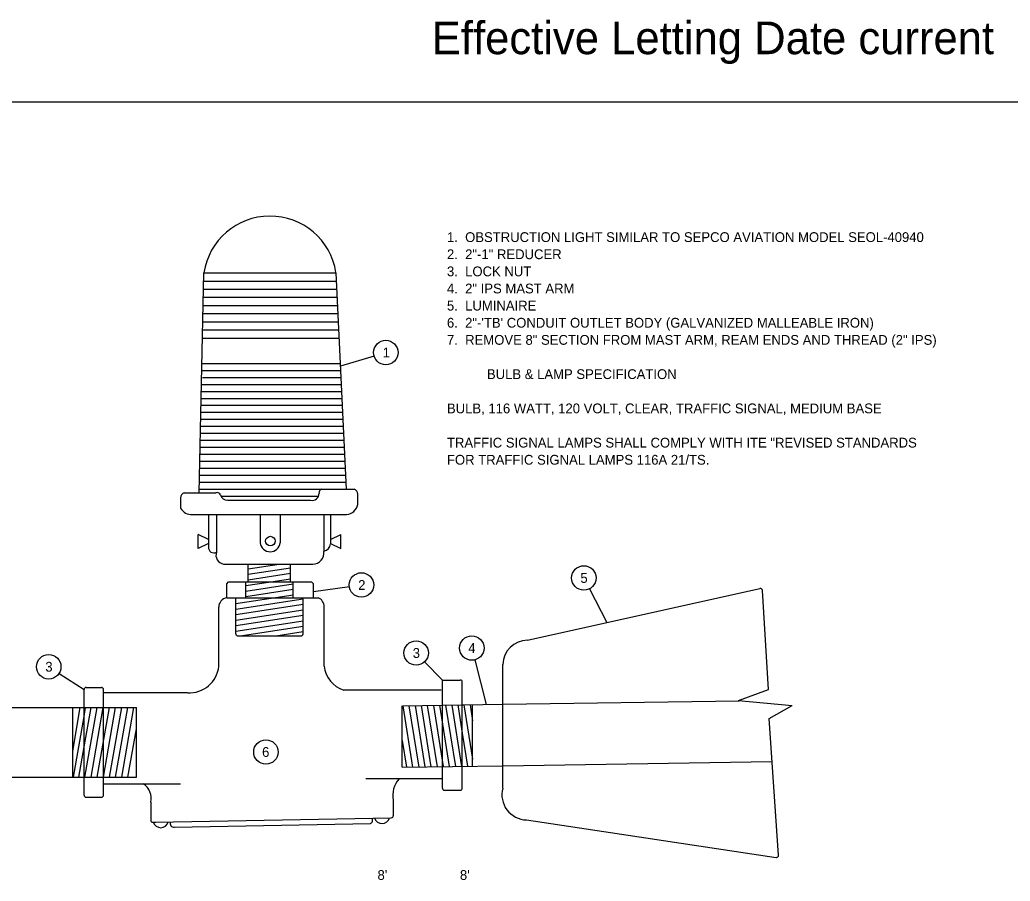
# Model space of a CAD drawing. Extents: x 99968 to 128667, y 90163 to 102182.
# Drawn here: x 106253 to 107468, y 101126 to 102182 of the extents above; entities that cross this region are included whole.
import ezdxf

# ---------------------------------------------------------------- set-up
doc = ezdxf.new("R2010")
doc.units = 0
for name, color, linetype in [('Default', 7, 'Continuous'), ('Level 7', 7, 'Continuous'), ('RD Standard Plans Active', 7, 'Continuous')]:
    doc.layers.add(name, color=color, linetype=linetype)

msp = doc.modelspace()

# ---------------------------------------------------------------- linework, layer by layer
at = {"layer": 'Default'}
msp.add_lwpolyline([(105067.5, 102081.5), (108267.2, 102081.5), (108267.2, 99881.9), (105067.5, 99881.9)], close=True, dxfattribs=at)
at = {"layer": 'RD Standard Plans Active'}
for p, q in [((106473.5, 101602.3), (106479.2, 101871.9)), ((106479.2, 101871.9), (106641.4, 101871.9)), ((106654.3, 101606.8), (106641.4, 101871.9)), ((106479.2, 101861.9), (106641.9, 101861.9)), ((106479.2, 101851.9), (106642.4, 101851.9)), ((106479.2, 101841.9), (106642.8, 101841.9)), ((106478.2, 101821.9), (106643.8, 101821.9)), ((106479.2, 101831.9), (106643.3, 101831.9)), ((106478, 101811.9), (106644.3, 101811.9)), ((106477.8, 101801.9), (106644.8, 101801.9)), ((106477.5, 101791.9), (106645.3, 101791.9)), ((106477.5, 101760.9), (106646.8, 101760.9)), ((106688, 101769.8), (106647, 101757.3)), ((106477.5, 101752.3), (106647.2, 101752.3)), ((106477.5, 101743.7), (106647.6, 101743.7)), ((106476.2, 101726.6), (106648.5, 101726.6)), ((106476.3, 101735.2), (106648.1, 101735.2)), ((106476, 101718), (106648.9, 101718)), ((106475.6, 101700.9), (106649.7, 101700.9)), ((106475.8, 101709.5), (106649.3, 101709.5)), ((106475.4, 101692.4), (106650.1, 101692.4)), ((106475.1, 101675.2), (106651, 101675.2)), ((106475.3, 101683.8), (106650.6, 101683.8)), ((106474.9, 101666.7), (106651.4, 101666.7)), ((106474.7, 101658.1), (106651.8, 101658.1)), ((106474.3, 101641), (106652.6, 101641)), ((106474.5, 101649.6), (106652.2, 101649.6)), ((106474.2, 101632.4), (106653.1, 101632.4)), ((106473.8, 101615.3), (106653.9, 101615.3)), ((106474, 101623.9), (106653.5, 101623.9)), ((106455, 101602.3), (106494.1, 101602.3)), ((106473.6, 101606.8), (106663.7, 101606.8)), ((106450.8, 101583.5), (106450.8, 101596.1)), ((106500.1, 101598.2), (106619.9, 101598.2)), ((106508.1, 101593.1), (106610.1, 101593.1)), ((106667.9, 101588), (106667.9, 101600.5)), ((106465, 101575.6), (106654.3, 101575.6)), ((106485, 101575.6), (106485, 101535.8)), ((106494.7, 101575.6), (106494.7, 101529.5)), ((106548.3, 101575.6), (106548.3, 101541)), ((106572.9, 101575.6), (106572.9, 101541)), ((106626.4, 101575.6), (106626.4, 101530.2)), ((106634.5, 101575.6), (106634.5, 101539.8)), ((106485, 101545.1), (106472.3, 101551.1)), ((106472.3, 101534), (106472.3, 101551.1)), ((106634.5, 101545.1), (106647.2, 101551.1)), ((106647.2, 101534), (106647.2, 101551.1)), ((106485, 101540.1), (106472.3, 101534)), ((106634.5, 101540.1), (106647.2, 101534)), ((106503.4, 101514.9), (106612.8, 101514.9)), ((106533.6, 101493.1), (106533.6, 101514.9)), ((106533.6, 101509), (106571.6, 101514.9)), ((106533.6, 101502.3), (106585.6, 101510.3)), ((106585.6, 101493.1), (106585.6, 101514.9)), ((106507.2, 101490.7), (106509.6, 101493.1)), ((106509.6, 101493.1), (106611.3, 101493.1)), ((106530.5, 101473.4), (106530.5, 101493.1)), ((106530.5, 101488.4), (106561.3, 101493.1)), ((106533.6, 101495.6), (106585.6, 101503.6)), ((106561.3, 101493.1), (106585.6, 101496.9)), ((106588.8, 101473.4), (106588.8, 101493.1)), ((106611.3, 101493.1), (106613.7, 101490.7)), ((106507.2, 101474.4), (106507.2, 101490.7)), ((106530.5, 101481.6), (106588.8, 101490.6)), ((106530.5, 101474.9), (106588.8, 101483.9)), ((106613.7, 101473.4), (106613.7, 101490.7)), ((106657.7, 101487), (106613.7, 101480.6)), ((106876.1, 101421.6), (107161.4, 101484.7)), ((106952.1, 101484.5), (106973.5, 101443.1)), ((107171.9, 101361.1), (107164.3, 101482.5)), ((106507.2, 101473.4), (106619.4, 101473.4)), ((106518.4, 101466.3), (106588.8, 101477.2)), ((106518.4, 101429.2), (106518.4, 101473.4)), ((106518.4, 101459.6), (106600.9, 101472.3)), ((106600.9, 101429.2), (106600.9, 101473.4)), ((106497.5, 101389.5), (106497.5, 101461.9)), ((106518.4, 101452.8), (106600.9, 101465.6)), ((106518.4, 101446.1), (106600.9, 101458.9)), ((106626.8, 101389.5), (106626.8, 101462.5)), ((106518.4, 101439.4), (106600.9, 101452.2)), ((106518.4, 101432.7), (106600.9, 101445.4)), ((106523.8, 101426.8), (106600.9, 101438.7)), ((106567.3, 101426.8), (106600.9, 101432)), ((106520.8, 101426.8), (106598.5, 101426.8)), ((106811.6, 101397.4), (106825.5, 101342.6)), ((106750, 101395), (106771.8, 101372.6)), ((106845.8, 101240), (106845.8, 101391.8)), ((106301.5, 101380.8), (106332.3, 101361.1)), ((106771.8, 101240), (106771.8, 101372.6)), ((106771.8, 101372.6), (106793.8, 101372.6)), ((106332.3, 101231.4), (106332.3, 101361.1)), ((106334.7, 101363.5), (106353.7, 101363.5)), ((106356.1, 101231.4), (106356.1, 101361.1)), ((106770.4, 101360.4), (106650.7, 101360.4)), ((106796.2, 101240), (106796.2, 101370.2)), ((107135.2, 101347.4), (107171.9, 101361.1)), ((106459.3, 101357.1), (106356.1, 101357.1)), ((106845.8, 101342.9), (107135.8, 101347.3)), ((107135.2, 101347.4), (107201, 101341.6)), ((106173, 101339), (106396.4, 101339)), ((106318.3, 101253.5), (106318.3, 101339)), ((106318.3, 101285.6), (106327.6, 101339)), ((106332.3, 101290.6), (106340.8, 101339)), ((106332.3, 101328), (106334.2, 101339)), ((106333.3, 101253.5), (106348.3, 101339)), ((106340.8, 101253.5), (106355.8, 101339)), ((106348.4, 101253.5), (106363.3, 101339)), ((106355.9, 101253.5), (106370.9, 101339)), ((106363.4, 101253.5), (106378.4, 101339)), ((106370.9, 101253.5), (106385.9, 101339)), ((106378.5, 101253.5), (106393.4, 101339)), ((106396.4, 101253.5), (106396.4, 101339)), ((106722.6, 101265.7), (106722.6, 101341)), ((106722.7, 101341), (106845.8, 101342.9)), ((106723.3, 101341), (106735.3, 101265.9)), ((106730.8, 101341.1), (106742.8, 101266)), ((106738.3, 101341.3), (106750.3, 101266.1)), ((106745.8, 101341.4), (106757.7, 101266.2)), ((106753.2, 101341.5), (106765.2, 101266.4)), ((106760.7, 101341.6), (106772.7, 101266.5)), ((106768.2, 101341.7), (106780.2, 101266.6)), ((106775.7, 101341.8), (106787.7, 101266.7)), ((106783.2, 101341.9), (106795.2, 101266.8)), ((106790.7, 101342.1), (106796.2, 101307.3)), ((106798.2, 101342.2), (106808.8, 101275.5)), ((106805.7, 101342.3), (106808.8, 101322.5)), ((106808.8, 101267), (106808.8, 101342.3)), ((107172.5, 101325.3), (107201, 101341.6)), ((106319.2, 101253.5), (106332.3, 101328)), ((107184.1, 101157.8), (107172.5, 101325.3)), ((106386, 101253.5), (106396.4, 101312.9)), ((106722.6, 101298.4), (106727.8, 101265.8)), ((106796.2, 101307.3), (106802.7, 101266.9)), ((106325.8, 101253.5), (106332.3, 101290.6)), ((106722.6, 101265.7), (106845.8, 101267.6)), ((106845.8, 101267.6), (107176.1, 101272.6)), ((106166.9, 101253.5), (106396.4, 101253.5)), ((106771.8, 101251.6), (106678, 101251.6)), ((106356.1, 101245.3), (106450.4, 101245.3)), ((106774.2, 101237.6), (106793.8, 101237.6)), ((106334.7, 101229), (106353.7, 101229)), ((106711.5, 101225.4), (106711.5, 101206.1)), ((106414.1, 101222.8), (106414.1, 101200.6)), ((106419.7, 101198.2), (106709.1, 101203.7)), ((106874.8, 101201.1), (107181.4, 101155.2)), ((106416.5, 101198.2), (106419.7, 101198.2)), ((106443, 101192.2), (106683.6, 101196.7))]:
    msp.add_line(p, q, dxfattribs=at)
for centre, radius in [((106702.4, 101774.2), 15), ((106560.8, 101543), 5.85), ((106945.3, 101497.8), 15), ((106672.5, 101489.2), 15), ((106739.6, 101405.8), 15), ((106807.9, 101411.9), 15), ((106288.9, 101388.9), 15), ((106555.3, 101284.4), 15)]:
    msp.add_circle(centre, radius, dxfattribs=at)
for centre, radius, start, end in [((106560.3, 101859.5), 82, 9.1108, 171.2968), ((106457.4, 101596.1), 6.68, 111.5466, 180.2747), ((106495.2, 101597.5), 4.95, 24.8139, 103.4873), ((106625.4, 101602.1), 4.96, 108.6782, 184.9831), ((106661.2, 101600.5), 6.68, 359.7253, 68.4534), ((106507.8, 101601.5), 8.37, 193.2443, 271.7731), ((106612.1, 101601.2), 8.37, 256.1498, 2.7045), ((106463.8, 101590.2), 14.7, 207.0933, 274.4503), ((106653.4, 101590.2), 14.7, 273.6739, 351.2469), ((106491.4, 101535), 6.42, 172.906, 301.1237), ((106504.9, 101525.7), 10.9, 159.6534, 262.1622), ((106560.6, 101542.4), 12.4, 186.3939, 353.6061), ((106613, 101528.4), 13.5, 269.2244, 7.6495), ((106624.6, 101540.4), 9.92, 280.4093, 356.3243), ((107161.9, 101482.4), 2.4, 3.589, 102.4771), ((106508.9, 101462.1), 11.4, 98.6121, 181.3159), ((106615.4, 101462.7), 11.4, 358.6841, 69.4614), ((106520.8, 101429.2), 2.4, 180, 270), ((106598.5, 101429.2), 2.4, 270, 0), ((106877.1, 101390.3), 31.4, 91.8902, 177.1357), ((106461.5, 101393.2), 36.2, 266.5758, 354.0187), ((106661, 101393.2), 34.4, 185.9813, 252.6714), ((106793.8, 101370.2), 2.4, 0, 90), ((106334.7, 101361.1), 2.4, 90, 180), ((106353.7, 101361.1), 2.4, 0, 90), ((106740.8, 101231.5), 29.9, 137.8013, 191.7004), ((106392.7, 101227.3), 21.9, 348.1233, 55.2495), ((106774.2, 101240), 2.4, 180, 270), ((106793.8, 101240), 2.4, 270, 0), ((106875.7, 101232), 30.9, 165.0516, 268.3332), ((106334.7, 101231.4), 2.4, 180, 270), ((106353.7, 101231.4), 2.4, 270, 0), ((106697.7, 101206.2), 9.47, 197.8889, 344.2804), ((106709.1, 101206.1), 2.4, 271.0868, 0), ((106416.5, 101200.6), 2.4, 180, 270), ((106426.2, 101201.1), 9.47, 197.8889, 344.2804), ((106442.4, 101196.7), 4.57, 155.6632, 277.5039), ((107181.8, 101157.6), 2.4, 261.4814, 3.9915)]:
    msp.add_arc(centre, radius, start, end, dxfattribs=at)
msp.add_ellipse((106682, 101201.7), major_axis=(-1.83, 4.85), ratio=0.784406, start_param=3.034399, end_param=4.712389, dxfattribs=at)

# ---------------------------------------------------------------- texts
at = {"layer": 'Level 7'}
msp.add_text('Effective Letting Date current', height=40, dxfattribs=at).set_placement((106758.8, 102140))
at = {"layer": 'RD Standard Plans Active'}
for s, p in [('1.  OBSTRUCTION LIGHT SIMILAR TO SEPCO AVIATION MODEL SEOL-40940', (106777.4, 101909.7)), ('2.  2"-1" REDUCER', (106777.4, 101888.7)), ('3.  LOCK NUT', (106777.4, 101867.7)), ('4.  2" IPS MAST ARM', (106777.4, 101846.7)), ('5.  LUMINAIRE', (106777.4, 101825.7)), ('6.  2"-\'TB\' CONDUIT OUTLET BODY (GALVANIZED MALLEABLE IRON)', (106777.4, 101804.7)), ('7.  REMOVE 8" SECTION FROM MAST ARM, REAM ENDS AND THREAD (2" IPS)', (106777.4, 101783.7)), ('1', (106698.5, 101768.2)), ('           BULB & LAMP SPECIFICATION', (106777.4, 101741.7)), ('BULB, 116 WATT, 120 VOLT, CLEAR, TRAFFIC SIGNAL, MEDIUM BASE', (106777.4, 101699.7)), ('TRAFFIC SIGNAL LAMPS SHALL COMPLY WITH ITE "REVISED STANDARDS', (106777.4, 101657.7)), ('FOR TRAFFIC SIGNAL LAMPS 116A 21/TS. ', (106777.4, 101636.7)), ('2', (106668.5, 101483.2)), ('5', (106941.1, 101491.8)), ('3', (106735.4, 101399.8)), ('4', (106803.5, 101405.9)), ('3', (106284.7, 101382.9)), ('6', (106550.6, 101278.4)), ("8'", (106692.2, 101127.6)), ("8'", (106793.3, 101127.6))]:
    msp.add_text(s, height=12, dxfattribs=at).set_placement(p)

doc.saveas('drawing.dxf')
